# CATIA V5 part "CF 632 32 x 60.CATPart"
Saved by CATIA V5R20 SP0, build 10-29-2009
Part number: CF 632 32 x 60
Definition: NONE
Nomenclature: CF 632 32 x 60
Source: Unknown
Description: CF 632 32 x 60
Bounding box of the stored display mesh (mm): x -13 to 47, y -26.5 to 26.5, z -26.5 to 26.5
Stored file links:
  C:\Users\Utente\Desktop\IO LAVORO\3D X SITO CF\X SITO\CF 632\CF 632 32 x 60.CATPart
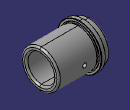
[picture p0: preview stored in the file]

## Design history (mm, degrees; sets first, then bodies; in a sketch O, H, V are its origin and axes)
Body1 "CF 632 32 x 60" (main body)
  Solid1: solid without history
